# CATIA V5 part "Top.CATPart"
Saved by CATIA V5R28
Part number: Top
Material "DS Dark Green": density 7860 kg/m3, Young's modulus 2e+11 Pa, Poisson ratio 0.266
Bounding box of the stored display mesh (mm): x -125 to 125, y -37.5 to 37.5, z -3 to 55
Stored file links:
  C:\Users\Parisa\Desktop\tarah sanat\CAR JACK\Top.CATPart
  C:\Program Files\Dassault Systemes\B28\win_b64\startup\materials\green_env_512x512.jpg
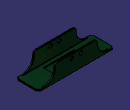
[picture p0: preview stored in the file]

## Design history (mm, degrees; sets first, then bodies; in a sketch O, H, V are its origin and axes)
Body1 (main body)
  Sketch1 on xy-plane, origin (0, 0, 0), H (1, 0, 0), V (0, 1, 0)
    line L1 (125, 27.5) -> (125, -27.5)
    line L2 (120, -32.5) -> (-120, -32.5)
    line L3 (-125, -27.5) -> (-125, 27.5)
    line L4 (-120, 32.5) -> (120, 32.5)
    arc A1 centre (120, 27.5) radius 5 from (125, 27.5) to (120, 32.5) ccw
    arc A2 centre (120, -27.5) radius 5 from (125, -27.5) to (120, -32.5) cw
    arc A3 centre (-120, -27.5) radius 5 from (-120, -32.5) to (-125, -27.5) cw
    arc A4 centre (-120, 27.5) radius 5 from (-125, 27.5) to (-120, 32.5) cw
    distance L4 L2 = 65
    distance L1 L3 = 250
    radius A1 = 5
    radius A2 = 5
    radius A3 = 5
    radius A4 = 5
    vertical: L1 V, L3 V
    horizontal: L2 H, L4 H
    equidistance: L1 L3 O, L2 L4 O
    tangency: A1 L1, A1 L4, A2 L1, A2 L2, A3 L2, A3 L3, A4 L3, A4 L4
  Pad1: profile Sketch1, direction (0, 0, 1), length 5
  Sketch2 on face of Pad1 from Sketch1.L4, origin (0, 32.5, 0), H (-1, 0, 0), V (0, 0, 1)
    point P1 (-120, 5)
    line L1 (-120, 5) -> (-120, 0)
    point P2 (-120, 0)
    line L2 (-120, 0) -> (120, 0)
    line L3 (120, 0) -> (120, 5)
    point P4 (120, 5)
    line L4 (120, 5) -> (107.9583, 5)
    point P5 (107.9583, 5)
    arc A1 centre (107.9583, 43) radius 38 from (107.9583, 5) to (69.9913, 44.5833) cw
    point P7 (69.9913, 44.5833)
    arc A2 centre (60, 45) radius 10 from (69.9913, 44.5833) to (60, 55) ccw
    point P9 (60, 55)
    line L5 (60, 55) -> (0, 55)
    point P10 (0, 55)
    reference projected line E1 (120, 0) -> (120, 5) from edge [face of Pad1 from Sketch1.A4 | face of Pad1 from Sketch1.L4]
    reference projected line E2 (-120, 5) -> (120, 5) from edge [face of Pad1 from Sketch1.L4 | end face of Pad1]
    reference projected line E3 (-120, 0) -> (-120, 5) from edge [face of Pad1 from Sketch1.L4 | face of Pad1 from Sketch1.A1]
    point P11 (-107.9583, 5)
    point P12 (-120, 5)
    line L6 (-120, 5) -> (-107.9583, 5)
    point P13 (-69.9913, 44.5833)
    arc A3 centre (-107.9583, 43) radius 38 from (-107.9583, 5) to (-69.9913, 44.5833) ccw
    point P15 (-60, 55)
    arc A4 centre (-60, 45) radius 10 from (-69.9913, 44.5833) to (-60, 55) cw
    point P17 (0, 55)
    line L7 (-60, 55) -> (0, 55)
    circle A5 centre (-15, 43) radius 5
    point P18 (-15, 43)
    circle A6 centre (15, 43) radius 5
    radius A2 = 10
    radius A1 = 38
    distance L5 L2 = 55
    length L5 = 60
    radius A5 = 5
    distance P18 V = 15
    distance P18 L7 = 12
    coincidence: P2 H, P10 V, L3 E1, L4 E2, L1 E3, P1 P12, P10 P17
    vertical: L1 V, L3 V
    horizontal: L2 H, L4 H
    tangency: A1 L4, A2 A1, L5 A2, L6 A3
    symmetry: P5 P11 V, P4 P12 V, L4 L6 V, P7 P13 V, A1 A3 V, P9 P15 V, A2 A4 V, P10 P17 V, L5 L7 V, A5 A6 V
  Pad2: profile Sketch2, direction (0, 1, 0), length 5
  Mirror1: of Pad2, about zx-plane
  Sketch3 on face of Pad2, origin (0, 0, 5), H (1, 0, 0), V (0, 1, 0)
    line L1 (50, 20) -> (50, -20)
    line L2 (50, -20) -> (-50, -20)
    line L3 (-50, -20) -> (-50, 20)
    line L4 (-50, 20) -> (50, 20)
    length L1 = 40
    length L4 = 100
    vertical: L1 V, L3 V
    horizontal: L2 H, L4 H
    equidistance: L1 L3 O, L2 L4 O
  Pocket1: profile Sketch3, direction (0, 0, -1), length 2
  Sketch4 on face of Pad2, origin (0, 0, 0), H (1, 0, 0), V (0, -1, 0)
    circle A1 centre (0, 0) radius 25
    radius A1 = 25
  Pad3: profile Sketch4, direction (0, 0, -1), length 3
  AutoFillet1: AutoFilletRadius 1, CurvatureRadius 1, RoundRadius 1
